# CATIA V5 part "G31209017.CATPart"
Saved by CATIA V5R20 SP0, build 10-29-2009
Part number: G31209017
Revision: 24
Definition: design
Nomenclature: G31209017
Source: made
Description: NOT SPECIFIED
Bounding box of the stored display mesh (mm): x -5 to 17, y -8 to 8, z -8 to 8
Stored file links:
  C:\Users\Raffaele\Desktop\3D X SITO CF\BOLEX\23-BUSH REF 312\G31209017.CATPart
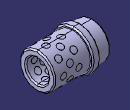
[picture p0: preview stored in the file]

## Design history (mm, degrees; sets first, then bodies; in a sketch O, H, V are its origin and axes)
Body1 "MANIFOLD_SOLID_BREP #3459" (main body)
  Solid1: solid without history
Body2 "MANIFOLD_SOLID_BREP #3602"
  Solid2: solid without history
Body3 "MANIFOLD_SOLID_BREP #3745"
  Solid3: solid without history
Body4 "MANIFOLD_SOLID_BREP #3888"
  Solid4: solid without history
Body5 "MANIFOLD_SOLID_BREP #4031"
  Solid5: solid without history
Body6 "MANIFOLD_SOLID_BREP #4174"
  Solid6: solid without history
Body7 "MANIFOLD_SOLID_BREP #4317"
  Solid7: solid without history
Body8 "MANIFOLD_SOLID_BREP #4462"
  Solid8: solid without history
Body9 "MANIFOLD_SOLID_BREP #4607"
  Solid9: solid without history
Body10 "MANIFOLD_SOLID_BREP #4752"
  Solid10: solid without history
Body11 "MANIFOLD_SOLID_BREP #4897"
  Solid11: solid without history
Body12 "MANIFOLD_SOLID_BREP #5040"
  Solid12: solid without history
Body13 "MANIFOLD_SOLID_BREP #5183"
  Solid13: solid without history
Body14 "MANIFOLD_SOLID_BREP #5328"
  Solid14: solid without history
Body15 "MANIFOLD_SOLID_BREP #5473"
  Solid15: solid without history
Body16 "MANIFOLD_SOLID_BREP #5618"
  Solid16: solid without history
Body17 "MANIFOLD_SOLID_BREP #5763"
  Solid17: solid without history
Body18 "MANIFOLD_SOLID_BREP #5908"
  Solid18: solid without history
Body19 "MANIFOLD_SOLID_BREP #6051"
  Solid19: solid without history
Body20 "MANIFOLD_SOLID_BREP #6194"
  Solid20: solid without history
Body21 "MANIFOLD_SOLID_BREP #6339"
  Solid21: solid without history
Body22 "MANIFOLD_SOLID_BREP #6484"
  Solid22: solid without history
Body23 "MANIFOLD_SOLID_BREP #6629"
  Solid23: solid without history
Body24 "MANIFOLD_SOLID_BREP #6774"
  Solid24: solid without history
Body25 "MANIFOLD_SOLID_BREP #6919"
  Solid25: solid without history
